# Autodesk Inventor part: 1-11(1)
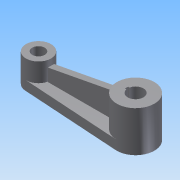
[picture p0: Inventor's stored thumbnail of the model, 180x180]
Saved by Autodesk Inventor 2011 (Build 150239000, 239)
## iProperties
Created: 2014-02
Part Number: 1-11(1)
Document SubType Name: Modeling
Designer: Administrator
Density: 1 g/cm^3
Author: Administrator
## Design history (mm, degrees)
sketch "草图1"
  geometry: L1 (-15.5, -4)-(15.111, -5.987); L2 (-15.5, 4)-(15.111, 5.987); A1 r 4 centre (-15.5, 0) between (-15.5, 4) and (-15.5, -4); A2 r 6 centre (15.5, 0) between (15.111, -5.987) and (15.111, 5.987); 2 further points
  constraints: 4 end point, 4 point on circle, 2 centre point, 2 coincident, 2 tangent
  dimensions: "d0" = 8 diameter of A1; "d1" = 12 diameter of A2
extrude "拉伸1" new body sketch "草图1" distance "d2" = 3; taper "d3" = 0 deg
sketch "草图2"
  geometry: C1 r 6 at (15.5, 0); A1 r 4 centre (-15.5, 0) between (-15.5, 4) and (-15.5, -4) reference; A2 r 6 centre (15.5, 0) between (15.111, -5.987) and (15.111, 5.987) reference; 2 further points
  constraints: 2 coincident, 1 centre point, 1 concentric, 1 vertical alignment, 2 other
extrude "拉伸2" join sketch "草图2" distance "d4" = 6; taper "d5" = 0 deg
sketch "草图3"
  geometry: C1 r 6 at (15.5, 0); A1 r 6 centre (15.5, 0) between (15.111, -5.987) and (15.111, 5.987) reference; 1 further point
  constraints: 1 centre point, 1 coincident, 1 concentric
extrude "拉伸3" join sketch "草图3" distance "d6" = 10; taper "d7" = 0 deg
sketch "草图4"
  geometry: C1 r 4 at (0, 0) reference; C2 r 2 at (0, 0); 1 further point
  constraints: 1 centre point, 1 coincident
  dimensions: "d8" = 4 diameter of C2
extrude "拉伸4" cut sketch "草图4" stored distance "d9" = 8; taper "d10" = 0 deg
sketch "草图5"
  geometry: L1 (-2.9, -0.5)-(-2.9, 0.5); L2 (-2.9, -0.5)-(-2.449, -0.5); L3 (-2.9, 0.5)-(-2.449, 0.5); C1 r 6 at (0, 0) reference; A1 r 2.5 centre (0, 0) between (-2.449, -0.5) and (-2.449, 0.5); 2 further points
  constraints: 6 end point, 2 point on circle, 1 centre point, 1 coincident, 1 horizontal alignment, 1 midpoint, 1 parallel, 1 perpendicular, 1 vertical
  dimensions: "d11" = 5 diameter of A1; "d12" = 1 distance of L1.start L1.end; "d17" = 2.9 distance from line of C1.centre L1
extrude "拉伸5" cut sketch "草图5" stored distance "d13" = 8; taper "d14" = 0 deg
sketch "草图6"
  geometry: L1 (11.5, 3)-(11.5, 9) reference; L2 (-9.5, 3)-(-9.5, 13) reference; L3 (11.5, 7)-(-9.5, 11); L4 (15.5, 3)-(-15.111, 3) reference; 1 further point
  constraints: 2 end point, 2 point on line
extrude "拉伸6" join sketch "草图6" stored distance "d15" = 2; taper "d16" = 0 deg
node "实体1"
